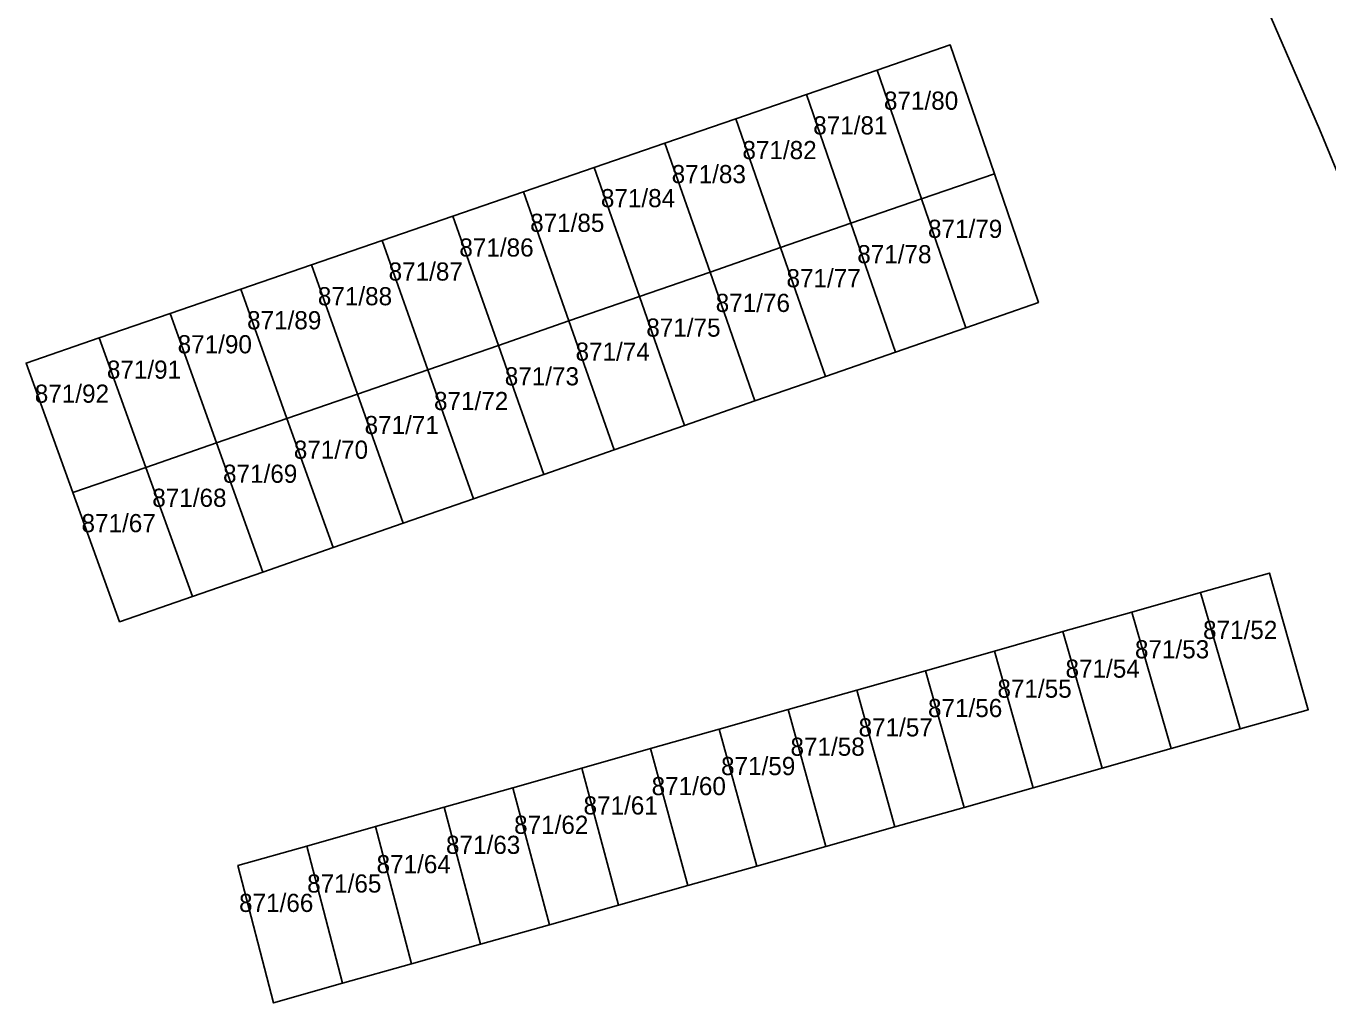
# Model space of a CAD drawing. Extents: x -873642 to -872917, y -1012962 to -1012567.
# Drawn here: x -873439.9 to -873378.9, y -1012916.8 to -1012871 of the extents above; entities that cross this region are included whole.
import ezdxf

# ---------------------------------------------------------------- set-up
doc = ezdxf.new("R2010")
doc.units = 0
for name, color, linetype in [('cisla_parcelni_kn', 7, 'Continuous'), ('parcely_kn', 7, 'Continuous'), ('stavebni_objekty_ostatni', 7, 'Continuous')]:
    doc.layers.add(name, color=color, linetype=linetype)

msp = doc.modelspace()

# ---------------------------------------------------------------- linework, layer by layer
at = {"layer": 'parcely_kn'}
for points in [[(-873379.34, -1012875.83), (-873373.58, -1012889.78), (-873355.03, -1012878.22), (-873289.09, -1012837.11), (-873306.1, -1012794.62), (-873364.45, -1012817.23), (-873371.7, -1012820.28), (-873376.39, -1012822.23), (-873378.27, -1012823.02), (-873378.61, -1012822.17), (-873388.38, -1012826.03), (-873398.8, -1012830.22), (-873398.3, -1012831.4), (-873382.99, -1012867.41)], [(-873379.34, -1012875.83), (-873373.58, -1012889.78), (-873355.03, -1012878.22), (-873289.09, -1012837.11), (-873306.1, -1012794.62), (-873364.45, -1012817.23), (-873371.7, -1012820.28), (-873376.39, -1012822.23), (-873378.27, -1012823.02), (-873378.61, -1012822.17), (-873388.38, -1012826.03), (-873398.8, -1012830.22), (-873398.3, -1012831.4), (-873382.99, -1012867.41)], [(-873355.03, -1012878.22), (-873373.58, -1012889.78), (-873379.34, -1012875.83), (-873382.99, -1012867.41), (-873398.3, -1012831.4), (-873398.8, -1012830.22), (-873388.38, -1012826.03), (-873378.61, -1012822.17), (-873378.27, -1012823.02), (-873376.39, -1012822.23), (-873370.46, -1012837.78), (-873381.76, -1012842.3), (-873375.46, -1012858.04), (-873364.42, -1012853.62)], [(-873355.03, -1012878.22), (-873373.58, -1012889.78), (-873379.34, -1012875.83), (-873382.99, -1012867.41), (-873398.3, -1012831.4), (-873398.8, -1012830.22), (-873388.38, -1012826.03), (-873378.61, -1012822.17), (-873378.27, -1012823.02), (-873376.39, -1012822.23), (-873370.46, -1012837.78), (-873381.76, -1012842.3), (-873375.46, -1012858.04), (-873364.42, -1012853.62)], [(-873435.5, -1012898.9), (-873432.09, -1012897.71), (-873428.8, -1012896.57), (-873425.51, -1012895.43), (-873422.22, -1012894.28), (-873418.93, -1012893.14), (-873415.64, -1012892), (-873412.35, -1012890.85), (-873409.05, -1012889.71), (-873405.76, -1012888.56), (-873402.46, -1012887.42), (-873399.18, -1012886.28), (-873395.89, -1012885.13), (-873392.49, -1012883.95), (-873394.55, -1012877.92), (-873396.62, -1012871.89), (-873400.04, -1012873.07), (-873403.35, -1012874.21), (-873406.66, -1012875.35), (-873409.97, -1012876.49), (-873413.28, -1012877.63), (-873416.59, -1012878.77), (-873419.9, -1012879.91), (-873423.21, -1012881.05), (-873426.52, -1012882.19), (-873429.83, -1012883.33), (-873433.14, -1012884.47), (-873436.45, -1012885.61), (-873439.88, -1012886.79), (-873437.69, -1012892.85)], [(-873435.5, -1012898.9), (-873432.09, -1012897.71), (-873428.8, -1012896.57), (-873425.51, -1012895.43), (-873422.22, -1012894.28), (-873418.93, -1012893.14), (-873415.64, -1012892), (-873412.35, -1012890.85), (-873409.05, -1012889.71), (-873405.76, -1012888.56), (-873402.46, -1012887.42), (-873399.18, -1012886.28), (-873395.89, -1012885.13), (-873392.49, -1012883.95), (-873394.55, -1012877.92), (-873396.62, -1012871.89), (-873400.04, -1012873.07), (-873403.35, -1012874.21), (-873406.66, -1012875.35), (-873409.97, -1012876.49), (-873413.28, -1012877.63), (-873416.59, -1012878.77), (-873419.9, -1012879.91), (-873423.21, -1012881.05), (-873426.52, -1012882.19), (-873429.83, -1012883.33), (-873433.14, -1012884.47), (-873436.45, -1012885.61), (-873439.88, -1012886.79), (-873437.69, -1012892.85)], [(-873396.62, -1012871.89), (-873394.55, -1012877.92), (-873397.96, -1012879.1), (-873400.04, -1012873.07)], [(-873396.62, -1012871.89), (-873394.55, -1012877.92), (-873397.96, -1012879.1), (-873400.04, -1012873.07)], [(-873397.96, -1012879.1), (-873401.27, -1012880.24), (-873403.35, -1012874.21), (-873400.04, -1012873.07)], [(-873397.96, -1012879.1), (-873401.27, -1012880.24), (-873403.35, -1012874.21), (-873400.04, -1012873.07)], [(-873403.35, -1012874.21), (-873401.27, -1012880.24), (-873404.56, -1012881.38), (-873406.66, -1012875.35)], [(-873403.35, -1012874.21), (-873401.27, -1012880.24), (-873404.56, -1012881.38), (-873406.66, -1012875.35)], [(-873404.56, -1012881.38), (-873407.86, -1012882.53), (-873409.97, -1012876.49), (-873406.66, -1012875.35)], [(-873404.56, -1012881.38), (-873407.86, -1012882.53), (-873409.97, -1012876.49), (-873406.66, -1012875.35)], [(-873409.97, -1012876.49), (-873407.86, -1012882.53), (-873411.16, -1012883.67), (-873413.28, -1012877.63)], [(-873409.97, -1012876.49), (-873407.86, -1012882.53), (-873411.16, -1012883.67), (-873413.28, -1012877.63)], [(-873411.16, -1012883.67), (-873414.47, -1012884.81), (-873416.59, -1012878.77), (-873413.28, -1012877.63)], [(-873411.16, -1012883.67), (-873414.47, -1012884.81), (-873416.59, -1012878.77), (-873413.28, -1012877.63)], [(-873394.55, -1012877.92), (-873392.49, -1012883.95), (-873395.89, -1012885.13), (-873397.96, -1012879.1)], [(-873394.55, -1012877.92), (-873392.49, -1012883.95), (-873395.89, -1012885.13), (-873397.96, -1012879.1)], [(-873416.59, -1012878.77), (-873414.47, -1012884.81), (-873417.77, -1012885.96), (-873419.9, -1012879.91)], [(-873416.59, -1012878.77), (-873414.47, -1012884.81), (-873417.77, -1012885.96), (-873419.9, -1012879.91)], [(-873395.89, -1012885.13), (-873399.18, -1012886.28), (-873401.27, -1012880.24), (-873397.96, -1012879.1)], [(-873395.89, -1012885.13), (-873399.18, -1012886.28), (-873401.27, -1012880.24), (-873397.96, -1012879.1)], [(-873417.77, -1012885.96), (-873421.07, -1012887.1), (-873423.21, -1012881.05), (-873419.9, -1012879.91)], [(-873417.77, -1012885.96), (-873421.07, -1012887.1), (-873423.21, -1012881.05), (-873419.9, -1012879.91)], [(-873401.27, -1012880.24), (-873399.18, -1012886.28), (-873402.46, -1012887.42), (-873404.56, -1012881.38)], [(-873401.27, -1012880.24), (-873399.18, -1012886.28), (-873402.46, -1012887.42), (-873404.56, -1012881.38)], [(-873423.21, -1012881.05), (-873421.07, -1012887.1), (-873424.37, -1012888.24), (-873426.52, -1012882.19)], [(-873423.21, -1012881.05), (-873421.07, -1012887.1), (-873424.37, -1012888.24), (-873426.52, -1012882.19)], [(-873402.46, -1012887.42), (-873405.76, -1012888.56), (-873407.86, -1012882.53), (-873404.56, -1012881.38)], [(-873402.46, -1012887.42), (-873405.76, -1012888.56), (-873407.86, -1012882.53), (-873404.56, -1012881.38)], [(-873424.37, -1012888.24), (-873427.67, -1012889.38), (-873429.83, -1012883.33), (-873426.52, -1012882.19)], [(-873424.37, -1012888.24), (-873427.67, -1012889.38), (-873429.83, -1012883.33), (-873426.52, -1012882.19)], [(-873407.86, -1012882.53), (-873405.76, -1012888.56), (-873409.05, -1012889.71), (-873411.16, -1012883.67)], [(-873407.86, -1012882.53), (-873405.76, -1012888.56), (-873409.05, -1012889.71), (-873411.16, -1012883.67)], [(-873429.83, -1012883.33), (-873427.67, -1012889.38), (-873430.97, -1012890.52), (-873433.14, -1012884.47)], [(-873429.83, -1012883.33), (-873427.67, -1012889.38), (-873430.97, -1012890.52), (-873433.14, -1012884.47)], [(-873409.05, -1012889.71), (-873412.35, -1012890.85), (-873414.47, -1012884.81), (-873411.16, -1012883.67)], [(-873409.05, -1012889.71), (-873412.35, -1012890.85), (-873414.47, -1012884.81), (-873411.16, -1012883.67)], [(-873430.97, -1012890.52), (-873434.27, -1012891.67), (-873436.45, -1012885.61), (-873433.14, -1012884.47)], [(-873430.97, -1012890.52), (-873434.27, -1012891.67), (-873436.45, -1012885.61), (-873433.14, -1012884.47)], [(-873414.47, -1012884.81), (-873412.35, -1012890.85), (-873415.64, -1012892), (-873417.77, -1012885.96)], [(-873414.47, -1012884.81), (-873412.35, -1012890.85), (-873415.64, -1012892), (-873417.77, -1012885.96)], [(-873436.45, -1012885.61), (-873434.27, -1012891.67), (-873437.69, -1012892.85), (-873439.88, -1012886.79)], [(-873436.45, -1012885.61), (-873434.27, -1012891.67), (-873437.69, -1012892.85), (-873439.88, -1012886.79)], [(-873415.64, -1012892), (-873418.93, -1012893.14), (-873421.07, -1012887.1), (-873417.77, -1012885.96)], [(-873415.64, -1012892), (-873418.93, -1012893.14), (-873421.07, -1012887.1), (-873417.77, -1012885.96)], [(-873421.07, -1012887.1), (-873418.93, -1012893.14), (-873422.22, -1012894.28), (-873424.37, -1012888.24)], [(-873421.07, -1012887.1), (-873418.93, -1012893.14), (-873422.22, -1012894.28), (-873424.37, -1012888.24)], [(-873422.22, -1012894.28), (-873425.51, -1012895.43), (-873427.67, -1012889.38), (-873424.37, -1012888.24)], [(-873422.22, -1012894.28), (-873425.51, -1012895.43), (-873427.67, -1012889.38), (-873424.37, -1012888.24)], [(-873427.67, -1012889.38), (-873425.51, -1012895.43), (-873428.8, -1012896.57), (-873430.97, -1012890.52)], [(-873427.67, -1012889.38), (-873425.51, -1012895.43), (-873428.8, -1012896.57), (-873430.97, -1012890.52)], [(-873430.97, -1012890.52), (-873428.8, -1012896.57), (-873432.09, -1012897.71), (-873434.27, -1012891.67)], [(-873430.97, -1012890.52), (-873428.8, -1012896.57), (-873432.09, -1012897.71), (-873434.27, -1012891.67)], [(-873434.27, -1012891.67), (-873432.09, -1012897.71), (-873435.5, -1012898.9), (-873437.69, -1012892.85)], [(-873434.27, -1012891.67), (-873432.09, -1012897.71), (-873435.5, -1012898.9), (-873437.69, -1012892.85)], [(-873383.04, -1012903.92), (-873379.86, -1012903.02), (-873381.68, -1012896.62), (-873384.9, -1012897.53), (-873388.12, -1012898.45), (-873391.34, -1012899.36), (-873394.55, -1012900.27), (-873397.77, -1012901.19), (-873400.99, -1012902.1), (-873404.21, -1012903.01), (-873407.43, -1012903.93), (-873410.65, -1012904.84), (-873413.87, -1012905.75), (-873417.09, -1012906.67), (-873420.3, -1012907.58), (-873423.52, -1012908.49), (-873426.74, -1012909.41), (-873429.96, -1012910.32), (-873428.3, -1012916.75), (-873425.07, -1012915.83), (-873421.83, -1012914.92), (-873418.6, -1012914), (-873415.37, -1012913.09), (-873412.14, -1012912.17), (-873408.9, -1012911.25), (-873405.67, -1012910.34), (-873402.44, -1012909.42), (-873399.21, -1012908.5), (-873395.97, -1012907.59), (-873392.74, -1012906.67), (-873389.51, -1012905.76), (-873386.28, -1012904.84)], [(-873383.04, -1012903.92), (-873379.86, -1012903.02), (-873381.68, -1012896.62), (-873384.9, -1012897.53), (-873388.12, -1012898.45), (-873391.34, -1012899.36), (-873394.55, -1012900.27), (-873397.77, -1012901.19), (-873400.99, -1012902.1), (-873404.21, -1012903.01), (-873407.43, -1012903.93), (-873410.65, -1012904.84), (-873413.87, -1012905.75), (-873417.09, -1012906.67), (-873420.3, -1012907.58), (-873423.52, -1012908.49), (-873426.74, -1012909.41), (-873429.96, -1012910.32), (-873428.3, -1012916.75), (-873425.07, -1012915.83), (-873421.83, -1012914.92), (-873418.6, -1012914), (-873415.37, -1012913.09), (-873412.14, -1012912.17), (-873408.9, -1012911.25), (-873405.67, -1012910.34), (-873402.44, -1012909.42), (-873399.21, -1012908.5), (-873395.97, -1012907.59), (-873392.74, -1012906.67), (-873389.51, -1012905.76), (-873386.28, -1012904.84)], [(-873384.9, -1012897.53), (-873381.68, -1012896.62), (-873379.86, -1012903.02), (-873383.04, -1012903.92)], [(-873384.9, -1012897.53), (-873381.68, -1012896.62), (-873379.86, -1012903.02), (-873383.04, -1012903.92)], [(-873388.12, -1012898.45), (-873384.9, -1012897.53), (-873383.04, -1012903.92), (-873386.28, -1012904.84)], [(-873388.12, -1012898.45), (-873384.9, -1012897.53), (-873383.04, -1012903.92), (-873386.28, -1012904.84)], [(-873391.34, -1012899.36), (-873388.12, -1012898.45), (-873386.28, -1012904.84), (-873389.51, -1012905.76)], [(-873391.34, -1012899.36), (-873388.12, -1012898.45), (-873386.28, -1012904.84), (-873389.51, -1012905.76)], [(-873394.55, -1012900.27), (-873391.34, -1012899.36), (-873389.51, -1012905.76), (-873392.74, -1012906.67)], [(-873394.55, -1012900.27), (-873391.34, -1012899.36), (-873389.51, -1012905.76), (-873392.74, -1012906.67)], [(-873397.77, -1012901.19), (-873394.55, -1012900.27), (-873392.74, -1012906.67), (-873395.97, -1012907.59)], [(-873397.77, -1012901.19), (-873394.55, -1012900.27), (-873392.74, -1012906.67), (-873395.97, -1012907.59)], [(-873400.99, -1012902.1), (-873397.77, -1012901.19), (-873395.97, -1012907.59), (-873399.21, -1012908.5)], [(-873400.99, -1012902.1), (-873397.77, -1012901.19), (-873395.97, -1012907.59), (-873399.21, -1012908.5)], [(-873404.21, -1012903.01), (-873400.99, -1012902.1), (-873399.21, -1012908.5), (-873402.44, -1012909.42)], [(-873404.21, -1012903.01), (-873400.99, -1012902.1), (-873399.21, -1012908.5), (-873402.44, -1012909.42)], [(-873407.43, -1012903.93), (-873404.21, -1012903.01), (-873402.44, -1012909.42), (-873405.67, -1012910.34)], [(-873407.43, -1012903.93), (-873404.21, -1012903.01), (-873402.44, -1012909.42), (-873405.67, -1012910.34)], [(-873410.65, -1012904.84), (-873407.43, -1012903.93), (-873405.67, -1012910.34), (-873408.9, -1012911.25)], [(-873410.65, -1012904.84), (-873407.43, -1012903.93), (-873405.67, -1012910.34), (-873408.9, -1012911.25)], [(-873413.87, -1012905.75), (-873410.65, -1012904.84), (-873408.9, -1012911.25), (-873412.14, -1012912.17)], [(-873413.87, -1012905.75), (-873410.65, -1012904.84), (-873408.9, -1012911.25), (-873412.14, -1012912.17)], [(-873417.09, -1012906.67), (-873413.87, -1012905.75), (-873412.14, -1012912.17), (-873415.37, -1012913.09)], [(-873417.09, -1012906.67), (-873413.87, -1012905.75), (-873412.14, -1012912.17), (-873415.37, -1012913.09)], [(-873420.3, -1012907.58), (-873417.09, -1012906.67), (-873415.37, -1012913.09), (-873418.6, -1012914)], [(-873420.3, -1012907.58), (-873417.09, -1012906.67), (-873415.37, -1012913.09), (-873418.6, -1012914)], [(-873423.52, -1012908.49), (-873420.3, -1012907.58), (-873418.6, -1012914), (-873421.83, -1012914.92)], [(-873423.52, -1012908.49), (-873420.3, -1012907.58), (-873418.6, -1012914), (-873421.83, -1012914.92)], [(-873426.74, -1012909.41), (-873423.52, -1012908.49), (-873421.83, -1012914.92), (-873425.07, -1012915.83)], [(-873426.74, -1012909.41), (-873423.52, -1012908.49), (-873421.83, -1012914.92), (-873425.07, -1012915.83)], [(-873429.96, -1012910.32), (-873426.74, -1012909.41), (-873425.07, -1012915.83), (-873428.3, -1012916.75)], [(-873429.96, -1012910.32), (-873426.74, -1012909.41), (-873425.07, -1012915.83), (-873428.3, -1012916.75)]]:
    msp.add_lwpolyline(points, close=True, dxfattribs=at)
at = {"layer": 'stavebni_objekty_ostatni'}
for points in [[(-873397.96, -1012879.1), (-873400.04, -1012873.07), (-873396.62, -1012871.89), (-873394.55, -1012877.92)], [(-873403.35, -1012874.21), (-873400.04, -1012873.07), (-873397.96, -1012879.1), (-873401.27, -1012880.24)], [(-873404.56, -1012881.38), (-873406.66, -1012875.35), (-873403.35, -1012874.21), (-873401.27, -1012880.24)], [(-873404.56, -1012881.38), (-873407.86, -1012882.53), (-873409.97, -1012876.49), (-873406.66, -1012875.35)], [(-873407.86, -1012882.53), (-873411.16, -1012883.67), (-873413.28, -1012877.63), (-873409.97, -1012876.49)], [(-873411.16, -1012883.67), (-873414.47, -1012884.81), (-873416.59, -1012878.77), (-873413.28, -1012877.63)], [(-873395.89, -1012885.13), (-873397.96, -1012879.1), (-873394.55, -1012877.92), (-873392.49, -1012883.95)], [(-873414.47, -1012884.81), (-873417.77, -1012885.96), (-873419.9, -1012879.91), (-873416.59, -1012878.77)], [(-873401.27, -1012880.24), (-873397.96, -1012879.1), (-873395.89, -1012885.13), (-873399.18, -1012886.28)], [(-873417.77, -1012885.96), (-873421.07, -1012887.1), (-873423.21, -1012881.05), (-873419.9, -1012879.91)], [(-873401.27, -1012880.24), (-873399.18, -1012886.28), (-873402.46, -1012887.42), (-873404.56, -1012881.38)], [(-873421.07, -1012887.1), (-873424.37, -1012888.24), (-873426.52, -1012882.19), (-873423.21, -1012881.05)], [(-873404.56, -1012881.38), (-873402.46, -1012887.42), (-873405.76, -1012888.56), (-873407.86, -1012882.53)], [(-873424.37, -1012888.24), (-873427.67, -1012889.38), (-873429.83, -1012883.33), (-873426.52, -1012882.19)], [(-873407.86, -1012882.53), (-873405.76, -1012888.56), (-873409.05, -1012889.71), (-873411.16, -1012883.67)], [(-873427.67, -1012889.38), (-873430.97, -1012890.52), (-873433.14, -1012884.47), (-873429.83, -1012883.33)], [(-873411.16, -1012883.67), (-873409.05, -1012889.71), (-873412.35, -1012890.85), (-873414.47, -1012884.81)], [(-873430.97, -1012890.52), (-873434.27, -1012891.67), (-873436.45, -1012885.61), (-873433.14, -1012884.47)], [(-873414.47, -1012884.81), (-873412.35, -1012890.85), (-873415.64, -1012892), (-873417.77, -1012885.96)], [(-873417.77, -1012885.96), (-873415.64, -1012892), (-873418.93, -1012893.14), (-873421.07, -1012887.1)], [(-873421.07, -1012887.1), (-873418.93, -1012893.14), (-873422.22, -1012894.28), (-873424.37, -1012888.24)], [(-873424.37, -1012888.24), (-873422.22, -1012894.28), (-873425.51, -1012895.43), (-873427.67, -1012889.38)], [(-873427.67, -1012889.38), (-873425.51, -1012895.43), (-873428.8, -1012896.57), (-873430.97, -1012890.52)], [(-873430.97, -1012890.52), (-873428.8, -1012896.57), (-873432.09, -1012897.71), (-873434.27, -1012891.67)], [(-873383.04, -1012903.92), (-873384.9, -1012897.53), (-873381.68, -1012896.62), (-873379.86, -1012903.02)], [(-873386.28, -1012904.84), (-873388.12, -1012898.45), (-873384.9, -1012897.53), (-873383.04, -1012903.92)], [(-873389.51, -1012905.76), (-873391.34, -1012899.36), (-873388.12, -1012898.45), (-873386.28, -1012904.84)], [(-873392.74, -1012906.67), (-873394.55, -1012900.27), (-873391.34, -1012899.36), (-873389.51, -1012905.76)], [(-873395.97, -1012907.59), (-873397.77, -1012901.19), (-873394.55, -1012900.27), (-873392.74, -1012906.67)], [(-873399.21, -1012908.5), (-873400.99, -1012902.1), (-873397.77, -1012901.19), (-873395.97, -1012907.59)], [(-873402.44, -1012909.42), (-873404.21, -1012903.01), (-873400.99, -1012902.1), (-873399.21, -1012908.5)], [(-873405.67, -1012910.34), (-873407.43, -1012903.93), (-873404.21, -1012903.01), (-873402.44, -1012909.42)], [(-873408.9, -1012911.25), (-873410.65, -1012904.84), (-873407.43, -1012903.93), (-873405.67, -1012910.34)], [(-873412.14, -1012912.17), (-873413.87, -1012905.75), (-873410.65, -1012904.84), (-873408.9, -1012911.25)], [(-873415.37, -1012913.09), (-873417.09, -1012906.67), (-873413.87, -1012905.75), (-873412.14, -1012912.17)], [(-873417.09, -1012906.67), (-873415.37, -1012913.09), (-873418.6, -1012914), (-873420.3, -1012907.58)], [(-873418.6, -1012914), (-873421.83, -1012914.92), (-873423.52, -1012908.49), (-873420.3, -1012907.58)], [(-873426.74, -1012909.41), (-873423.52, -1012908.49), (-873421.83, -1012914.92), (-873425.07, -1012915.83)]]:
    msp.add_lwpolyline(points, close=True, dxfattribs=at)

# ---------------------------------------------------------------- texts
at = {"layer": 'cisla_parcelni_kn'}
for s, p in [('871/80', (-873399.721, -1012874.925)), ('871/80', (-873399.721, -1012874.925)), ('871/81', (-873403.033, -1012876.081)), ('871/81', (-873403.033, -1012876.081)), ('871/82', (-873406.346, -1012877.238)), ('871/82', (-873406.346, -1012877.238)), ('871/83', (-873409.658, -1012878.363)), ('871/83', (-873409.658, -1012878.363)), ('871/84', (-873412.971, -1012879.488)), ('871/84', (-873412.971, -1012879.488)), ('871/85', (-873416.283, -1012880.644)), ('871/85', (-873416.283, -1012880.644)), ('871/79', (-873397.658, -1012880.925)), ('871/79', (-873397.658, -1012880.925)), ('871/86', (-873419.596, -1012881.8)), ('871/86', (-873419.596, -1012881.8)), ('871/78', (-873400.971, -1012882.113)), ('871/78', (-873400.971, -1012882.113)), ('871/87', (-873422.908, -1012882.925)), ('871/87', (-873422.908, -1012882.925)), ('871/77', (-873404.283, -1012883.238)), ('871/77', (-873404.283, -1012883.238)), ('871/88', (-873426.221, -1012884.081)), ('871/88', (-873426.221, -1012884.081)), ('871/76', (-873407.596, -1012884.394)), ('871/76', (-873407.596, -1012884.394)), ('871/89', (-873429.533, -1012885.206)), ('871/89', (-873429.533, -1012885.206)), ('871/75', (-873410.846, -1012885.55)), ('871/75', (-873410.846, -1012885.55)), ('871/90', (-873432.783, -1012886.331)), ('871/90', (-873432.783, -1012886.331)), ('871/74', (-873414.158, -1012886.675)), ('871/74', (-873414.158, -1012886.675)), ('871/91', (-873436.096, -1012887.519)), ('871/91', (-873436.096, -1012887.519)), ('871/73', (-873417.471, -1012887.831)), ('871/73', (-873417.471, -1012887.831)), ('871/92', (-873439.471, -1012888.644)), ('871/92', (-873439.471, -1012888.644)), ('871/72', (-873420.783, -1012888.988)), ('871/72', (-873420.783, -1012888.988)), ('871/71', (-873424.033, -1012890.113)), ('871/71', (-873424.033, -1012890.113)), ('871/70', (-873427.346, -1012891.269)), ('871/70', (-873427.346, -1012891.269)), ('871/69', (-873430.658, -1012892.394)), ('871/69', (-873430.658, -1012892.394)), ('871/68', (-873433.971, -1012893.519)), ('871/68', (-873433.971, -1012893.519)), ('871/67', (-873437.283, -1012894.706)), ('871/67', (-873437.283, -1012894.706)), ('871/52', (-873384.783, -1012899.706)), ('871/52', (-873384.783, -1012899.706)), ('871/53', (-873387.971, -1012900.613)), ('871/53', (-873387.971, -1012900.613)), ('871/54', (-873391.221, -1012901.519)), ('871/54', (-873391.221, -1012901.519)), ('871/55', (-873394.408, -1012902.456)), ('871/55', (-873394.408, -1012902.456)), ('871/56', (-873397.658, -1012903.363)), ('871/56', (-873397.658, -1012903.363)), ('871/57', (-873400.908, -1012904.269)), ('871/57', (-873400.908, -1012904.269)), ('871/58', (-873404.096, -1012905.175)), ('871/58', (-873404.096, -1012905.175)), ('871/59', (-873407.346, -1012906.081)), ('871/59', (-873407.346, -1012906.081)), ('871/60', (-873410.596, -1012907.019)), ('871/60', (-873410.596, -1012907.019)), ('871/61', (-873413.783, -1012907.925)), ('871/61', (-873413.783, -1012907.925)), ('871/62', (-873417.033, -1012908.831)), ('871/62', (-873417.033, -1012908.831)), ('871/63', (-873420.221, -1012909.769)), ('871/63', (-873420.221, -1012909.769)), ('871/64', (-873423.471, -1012910.675)), ('871/64', (-873423.471, -1012910.675)), ('871/65', (-873426.721, -1012911.581)), ('871/65', (-873426.721, -1012911.581)), ('871/66', (-873429.908, -1012912.488)), ('871/66', (-873429.908, -1012912.488))]:
    msp.add_text(s, height=0.85, dxfattribs=at).set_placement(p)

doc.saveas('drawing.dxf')
